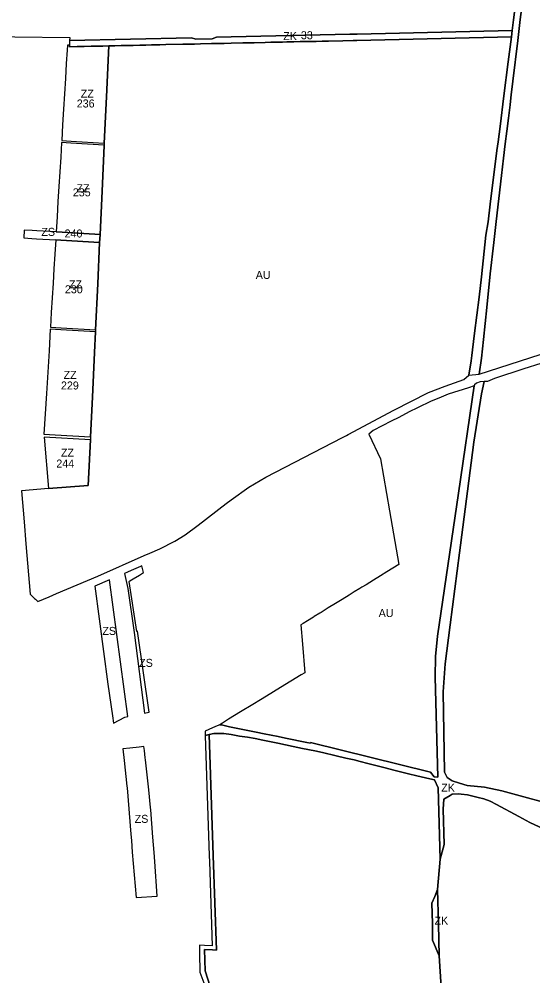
# Model space of a CAD drawing. Extents: x -521939 to -516426, y -1197857 to -1189551.
# Drawn here: x -519323 to -518681, y -1192149 to -1190954 of the extents above; entities that cross this region are included whole.
import ezdxf

# ---------------------------------------------------------------- set-up
doc = ezdxf.new("R2010")
doc.units = 0
for name, color, linetype in [('90660013', 7, 'Continuous'), ('90660023', 7, 'Continuous'), ('90670023', 7, 'Continuous'), ('90710013', 7, 'Continuous'), ('90710023', 7, 'Continuous'), ('90750013', 7, 'Continuous'), ('90760013', 7, 'Continuous'), ('ID_navrh', 7, 'Continuous')]:
    doc.layers.add(name, color=color, linetype=linetype)

msp = doc.modelspace()

# ---------------------------------------------------------------- linework, layer by layer
at = {"layer": '90660013'}
for points in [[(-519166.23, -1191821.08), (-519162.27, -1191820.28), (-519160.39, -1191819.9), (-519174.95, -1191718.57), (-519175.69, -1191719.09), (-519185.37, -1191656.34), (-519184.37, -1191655.72), (-519180.36, -1191653.25), (-519172.53, -1191648.41), (-519167.31, -1191645.19), (-519169.3, -1191636.96), (-519171.02, -1191637.8), (-519174.11, -1191639.14), (-519182.56, -1191642.78), (-519187.15, -1191644.77), (-519190.89, -1191646.39), (-519187.07, -1191665.36), (-519179.1, -1191720.15), (-519166.23, -1191821.08)], [(-519186.83, -1191825.25), (-519209.86, -1191654.59), (-519228.08, -1191662.46), (-519211.74, -1191784.69), (-519206.08, -1191824.4), (-519204.81, -1191833.46), (-519190.77, -1191826.05), (-519186.83, -1191825.25)], [(-519158.47, -1191938.79), (-519160.59, -1191916.77), (-519161.31, -1191909.45), (-519164.9, -1191879.38), (-519165.19, -1191876.73), (-519166.19, -1191867.57), (-519166.74, -1191862.69), (-519169.73, -1191863.03), (-519172.72, -1191863.37), (-519184.32, -1191864.69), (-519193.05, -1191865.68), (-519191.35, -1191880.2), (-519188.13, -1191912.11), (-519187.89, -1191914.5), (-519183.11, -1191972.15), (-519182.47, -1191980.22), (-519181.33, -1191994.8), (-519176.56, -1192051.51), (-519150.36, -1192049.88), (-519153.05, -1192006.54), (-519153.99, -1191995.08), (-519155.53, -1191975.95), (-519158.18, -1191941.83), (-519158.47, -1191938.79)]]:
    msp.add_lwpolyline(points, dxfattribs=at)
at = {"layer": '90660023'}
msp.add_lwpolyline([(-519277.03, -1191229.63), (-519270.66, -1191230.01), (-519222.12, -1191232.93), (-519221.9, -1191228.24), (-519221.65, -1191222.94), (-519269, -1191220.09), (-519276.43, -1191219.64), (-519300.38, -1191218.2), (-519306.37, -1191217.84), (-519316.35, -1191217.24), (-519316.95, -1191227.22), (-519306.97, -1191227.82), (-519300.98, -1191228.18), (-519277.03, -1191229.63)], dxfattribs=at)
at = {"layer": '90670023'}
for points in [[(-519269.55, -1191105.4), (-519257.89, -1191106.1), (-519216.29, -1191108.61), (-519213.59, -1191050.84), (-519210.6, -1190987.17), (-519218.24, -1190987.34), (-519232.69, -1190987.61), (-519241.28, -1190987.85), (-519250.24, -1190988.04), (-519259.96, -1190988.33), (-519259.89, -1190986.43), (-519262.38, -1190986.4), (-519262.74, -1190992.4), (-519263.74, -1191008.98), (-519264.88, -1191027.94), (-519266.03, -1191046.91), (-519267.2, -1191066.37), (-519268.37, -1191085.84), (-519269.55, -1191105.4)], [(-519269.7, -1191107.9), (-519270.8, -1191126.16), (-519271.9, -1191144.43), (-519273, -1191162.7), (-519274.14, -1191181.66), (-519275.28, -1191200.63), (-519276.43, -1191219.64), (-519269, -1191220.09), (-519221.65, -1191222.94), (-519219.11, -1191168.85), (-519216.44, -1191111.73), (-519216.41, -1191111.11), (-519258.03, -1191108.6), (-519269.7, -1191107.9)], [(-519277.03, -1191229.63), (-519278.11, -1191247.59), (-519279.19, -1191265.56), (-519280.27, -1191283.53), (-519281.38, -1191301.9), (-519282.48, -1191320.26), (-519283.59, -1191338.68), (-519270.38, -1191339.47), (-519227.23, -1191342.07), (-519227.23, -1191342.05), (-519224.53, -1191284.5), (-519222.12, -1191232.93), (-519270.66, -1191230.01), (-519277.03, -1191229.63)], [(-519233.5, -1191475.79), (-519231.17, -1191426.05), (-519228.55, -1191370.34), (-519227.35, -1191344.57), (-519270.52, -1191341.97), (-519283.74, -1191341.17), (-519285.37, -1191368.28), (-519286.98, -1191394.95), (-519288.59, -1191421.63), (-519290.11, -1191446.93), (-519291.64, -1191472.29), (-519277.54, -1191473.14), (-519233.5, -1191475.79)], [(-519285.93, -1191540.47), (-519236.33, -1191536.36), (-519233.67, -1191479.5), (-519291.33, -1191476), (-519285.93, -1191540.47)]]:
    msp.add_lwpolyline(points, dxfattribs=at)
at = {"layer": '90710013'}
for points in [[(-518701.87, -1190928.62), (-518705, -1190954.5), (-518706.73, -1190968.01), (-518707.73, -1190975.95), (-518711.69, -1191007.15), (-518717.06, -1191049.38), (-518721.96, -1191087.75), (-518724.35, -1191106.87), (-518725.79, -1191117.86), (-518734.23, -1191185.05), (-518736.94, -1191206.83), (-518739.49, -1191223.8), (-518745.15, -1191275.82), (-518748.04, -1191301.16), (-518750.85, -1191323.52), (-518753.72, -1191346.05), (-518756.3, -1191366.88), (-518757.28, -1191373.96), (-518758.12, -1191380.68), (-518760.85, -1191398.59), (-518747.87, -1191397.44), (-518744.99, -1191377.23), (-518742.65, -1191354.12), (-518738.65, -1191314.03), (-518734.1, -1191271.87), (-518729.7, -1191232.73), (-518726.85, -1191206.62), (-518720.19, -1191149.32), (-518717.56, -1191127.4), (-518715.46, -1191109.65), (-518713.5, -1191093.65), (-518711.56, -1191077.4), (-518709.5, -1191060.59), (-518707.98, -1191047.98), (-518706.78, -1191038.15), (-518705.95, -1191031.23), (-518699.77, -1190980.19), (-518696.61, -1190954.07), (-518693.43, -1190928.61)], [(-518754.2, -1191411.84), (-518773.85, -1191545.97), (-518800.05, -1191724.81), (-518802.68, -1191750.42), (-518803.08, -1191776.16), (-518799.63, -1191901.15), (-518804.16, -1191900.55), (-518808.94, -1191894.62), (-518958.64, -1191857.72), (-518958.57, -1191858.54), (-518963.29, -1191857.58), (-518989.74, -1191852.2), (-518999.26, -1191850.26), (-519016.52, -1191846.75), (-519026.54, -1191844.72), (-519043.1, -1191841.35), (-519059.82, -1191837.95), (-519068.41, -1191836.2), (-519072.06, -1191835.46), (-519077.48, -1191837.92), (-519085.67, -1191841.64), (-519090.29, -1191843.73), (-519090.29, -1191843.74), (-519090.12, -1191848.97), (-519085.16, -1191847.79), (-519079.37, -1191846.41), (-519066.92, -1191846.35), (-519057.75, -1191847.88), (-519047.43, -1191849.61), (-519037.5, -1191851.27), (-519028.03, -1191852.85), (-519018.37, -1191854.65), (-518999.64, -1191858.56), (-518989.78, -1191860.65), (-518980.39, -1191862.6), (-518968.88, -1191865.04), (-518953.17, -1191868.33), (-518943.85, -1191870.37), (-518926.69, -1191874.22), (-518914.51, -1191877.14), (-518904.31, -1191879.59), (-518896.54, -1191881.55), (-518887.24, -1191883.93), (-518865.4, -1191889.53), (-518854.47, -1191892.36), (-518836.4, -1191897), (-518825.73, -1191899.39), (-518809.6, -1191903.15), (-518803.99, -1191904.45), (-518799.28, -1191914.55), (-518796.83, -1192003.5), (-518791.91, -1191985.07), (-518793.12, -1191940.86), (-518792.23, -1191928.59), (-518784.35, -1191923.87), (-518781.86, -1191922.38), (-518774.41, -1191922.02), (-518770.47, -1191922.34), (-518762.46, -1191923.02), (-518749.45, -1191926.36), (-518742.23, -1191928.21), (-518734.3, -1191931.03), (-518726.43, -1191935.4), (-518698.42, -1191950.28), (-518684.53, -1191957.75), (-518662.07, -1191967.96)], [(-518640.22, -1191939.66), (-518719.73, -1191918.12), (-518741.25, -1191913.55), (-518763.14, -1191911.41), (-518772.54, -1191908.42), (-518781.94, -1191905.44), (-518787.95, -1191901.51), (-518791.36, -1191894.96), (-518792.8, -1191794.51), (-518790.3, -1191759.62), (-518784.24, -1191710.51), (-518772.41, -1191620.67), (-518762.61, -1191543.53), (-518754.85, -1191482.52), (-518745.17, -1191421.89), (-518741.69, -1191406.71), (-518746.71, -1191406.97), (-518751.45, -1191408.55), (-518753.93, -1191410.91), (-518754.2, -1191411.84)], [(-518797.81, -1192124.2), (-518798.92, -1192084.73), (-518800.13, -1192041.55), (-518800.16, -1192041.61), (-518803.56, -1192050.14), (-518806.95, -1192058.66), (-518806.95, -1192058.67), (-518806.52, -1192084.13), (-518806.17, -1192104.86), (-518797.81, -1192124.2)]]:
    msp.add_lwpolyline(points, dxfattribs=at)
at = {"layer": '90710023'}
for points in [[(-519259.89, -1190986.43), (-519259.96, -1190988.33), (-519250.24, -1190988.04), (-519241.28, -1190987.85), (-519232.69, -1190987.61), (-519218.24, -1190987.34), (-519210.6, -1190987.17), (-519202.99, -1190986.99), (-519195.39, -1190986.84), (-519180.12, -1190986.51), (-519171.98, -1190986.32), (-519164.58, -1190986.14), (-519157.3, -1190985.98), (-519146.73, -1190985.75), (-519139.45, -1190985.59), (-519118.38, -1190985.11), (-519103.75, -1190984.78), (-519096.18, -1190984.64), (-519082.46, -1190984.32), (-519074.13, -1190984.14), (-519066.62, -1190983.97), (-519057.96, -1190983.78), (-519043.29, -1190983.45), (-519036.25, -1190983.29), (-519029.04, -1190983.14), (-519015.53, -1190982.84), (-519008.2, -1190982.68), (-519001.41, -1190982.5), (-518993.81, -1190982.32), (-518988.21, -1190982.23), (-518979.42, -1190982.05), (-518971.69, -1190981.85), (-518960, -1190981.61), (-518951.6, -1190981.45), (-518943.98, -1190981.24), (-518936.34, -1190981.09), (-518918.12, -1190980.66), (-518905.51, -1190980.41), (-518900.98, -1190980.31), (-518707.73, -1190975.95), (-518706.73, -1190968.01), (-518900.54, -1190972.29), (-518905.06, -1190972.39), (-518909.73, -1190972.5), (-519076.07, -1190976.18), (-519081.68, -1190978.3), (-519101.85, -1190978.75), (-519107.55, -1190976.87), (-519259.67, -1190980.24), (-519259.89, -1190986.43)], [(-519083.86, -1192162.62), (-519090.14, -1192143.06), (-519091, -1192116.25), (-519081.24, -1192116.84), (-519076.23, -1192117.14), (-519080.14, -1191999.07), (-519085.16, -1191847.79), (-519090.12, -1191848.97), (-519085.14, -1191999.24), (-519084.89, -1192006.65), (-519081.41, -1192111.82), (-519091.16, -1192111.23), (-519097.51, -1192110.84), (-519097.34, -1192121.07), (-519096.85, -1192144.75), (-519088.41, -1192167.96)]]:
    msp.add_lwpolyline(points, dxfattribs=at)
at = {"layer": '90750013'}
for points in [[(-519397.29, -1190974.84), (-519259.53, -1190976.44), (-519259.67, -1190980.24), (-519107.55, -1190976.87), (-519101.85, -1190978.75), (-519081.68, -1190978.3), (-519076.07, -1190976.18), (-518909.73, -1190972.5), (-518905.06, -1190972.39), (-518900.54, -1190972.29), (-518706.73, -1190968.01), (-518705, -1190954.5), (-518701.87, -1190928.62)], [(-518693.43, -1190928.61), (-518696.61, -1190954.07), (-518699.77, -1190980.19), (-518705.95, -1191031.23), (-518706.78, -1191038.15), (-518707.98, -1191047.98), (-518709.5, -1191060.59), (-518711.56, -1191077.4), (-518713.5, -1191093.65), (-518715.46, -1191109.65), (-518717.56, -1191127.4), (-518720.19, -1191149.32), (-518726.85, -1191206.62), (-518729.7, -1191232.73), (-518734.1, -1191271.87), (-518738.65, -1191314.03), (-518742.65, -1191354.12), (-518744.99, -1191377.23), (-518747.87, -1191397.44), (-518607.36, -1191351.98)], [(-519233.5, -1191475.79), (-519233.67, -1191479.5), (-519236.33, -1191536.36), (-519285.93, -1191540.47), (-519319.78, -1191543.27), (-519316.54, -1191582.06), (-519314.27, -1191609.51), (-519309.03, -1191672.4), (-519303.32, -1191677.79), (-519302.34, -1191678.73), (-519299.42, -1191681.52), (-519285.21, -1191675.48), (-519275.99, -1191671.57), (-519224.33, -1191649.88), (-519166.49, -1191624.15), (-519159.42, -1191620.98), (-519146.78, -1191615.88), (-519128.1, -1191606.31), (-519115.32, -1191598.2), (-519099.08, -1191586.11), (-519064.09, -1191558.9), (-519057.88, -1191554.46), (-519035.9, -1191538.66), (-519014.69, -1191526.04), (-518918.69, -1191476.44), (-518913.57, -1191473.95), (-518911.56, -1191472.69), (-518854.76, -1191442.26), (-518811.46, -1191420.48), (-518790.63, -1191412.2), (-518767.05, -1191404.02), (-518760.85, -1191398.59), (-518758.12, -1191380.68), (-518757.28, -1191373.96), (-518756.3, -1191366.88), (-518753.72, -1191346.05), (-518750.85, -1191323.52), (-518748.04, -1191301.16), (-518745.15, -1191275.82), (-518739.49, -1191223.8), (-518736.94, -1191206.83), (-518734.23, -1191185.05), (-518725.79, -1191117.86), (-518724.35, -1191106.87), (-518721.96, -1191087.75), (-518717.06, -1191049.38), (-518711.69, -1191007.15), (-518707.73, -1190975.95), (-518900.98, -1190980.31), (-518905.51, -1190980.41), (-518918.12, -1190980.66), (-518936.34, -1190981.09), (-518943.98, -1190981.24), (-518951.6, -1190981.45), (-518960, -1190981.61), (-518971.69, -1190981.85), (-518979.42, -1190982.05), (-518988.21, -1190982.23), (-518993.81, -1190982.32), (-519001.41, -1190982.5), (-519008.2, -1190982.68), (-519015.53, -1190982.84), (-519029.04, -1190983.14), (-519036.25, -1190983.29), (-519043.29, -1190983.45), (-519057.96, -1190983.78), (-519066.62, -1190983.97), (-519074.13, -1190984.14), (-519082.46, -1190984.32), (-519096.18, -1190984.64), (-519103.75, -1190984.78), (-519118.38, -1190985.11), (-519139.45, -1190985.59), (-519146.73, -1190985.75), (-519157.3, -1190985.98), (-519164.58, -1190986.14), (-519171.98, -1190986.32), (-519180.12, -1190986.51), (-519195.39, -1190986.84), (-519202.99, -1190986.99), (-519210.6, -1190987.17), (-519213.59, -1191050.84), (-519216.29, -1191108.61), (-519216.41, -1191111.11), (-519216.44, -1191111.73), (-519219.11, -1191168.85), (-519221.65, -1191222.94), (-519221.9, -1191228.24), (-519222.12, -1191232.93), (-519224.53, -1191284.5), (-519227.23, -1191342.05), (-519227.23, -1191342.07), (-519227.35, -1191344.57), (-519228.55, -1191370.34), (-519231.17, -1191426.05), (-519233.5, -1191475.79)], [(-518754.2, -1191411.84), (-518761.48, -1191414.29), (-518786.77, -1191422.24), (-518798.48, -1191427.3), (-518808.08, -1191431.2), (-518824.92, -1191439.39), (-518835.63, -1191444.66), (-518848.51, -1191451.57), (-518857.88, -1191456.33), (-518880.29, -1191467.99), (-518885.93, -1191472.19), (-518871.38, -1191503.14), (-518860.03, -1191568.23), (-518848.35, -1191635.22), (-518855.68, -1191639.74), (-518863.57, -1191644.61), (-518871.47, -1191649.48), (-518880.15, -1191654.83), (-518889.34, -1191660.5), (-518894.63, -1191663.76), (-518897.28, -1191665.4), (-518904.04, -1191669.57), (-518909.18, -1191672.74), (-518910.35, -1191673.46), (-518919.14, -1191678.88), (-518927.34, -1191683.94), (-518936.55, -1191689.62), (-518945.5, -1191695.14), (-518947.13, -1191696.15), (-518954.06, -1191700.42), (-518955.12, -1191701.08), (-518962.41, -1191705.57), (-518968.04, -1191709.04), (-518970.94, -1191710.83), (-518968.91, -1191735.03), (-518965.94, -1191770.51), (-518970.55, -1191773.33), (-518996.05, -1191788.94), (-519004.95, -1191794.39), (-519019, -1191802.99), (-519021.11, -1191804.28), (-519030.85, -1191810.24), (-519046.06, -1191819.55), (-519061.07, -1191828.73), (-519068.8, -1191833.47), (-519072.06, -1191835.46), (-519068.41, -1191836.2), (-519059.82, -1191837.95), (-519043.1, -1191841.35), (-519026.54, -1191844.72), (-519016.52, -1191846.75), (-518999.26, -1191850.26), (-518989.74, -1191852.2), (-518963.29, -1191857.58), (-518958.57, -1191858.54), (-518958.64, -1191857.72), (-518808.94, -1191894.62), (-518804.16, -1191900.55), (-518799.63, -1191901.15), (-518803.08, -1191776.16), (-518802.68, -1191750.42), (-518800.05, -1191724.81), (-518773.85, -1191545.97), (-518754.2, -1191411.84)]]:
    msp.add_lwpolyline(points, dxfattribs=at)
at = {"layer": '90760013'}
for points in [[(-518671.16, -1191383.98), (-518692.08, -1191390.79), (-518728.9, -1191402.78), (-518737.43, -1191406.49), (-518741.69, -1191406.71), (-518745.17, -1191421.89), (-518754.85, -1191482.52), (-518762.61, -1191543.53), (-518772.41, -1191620.67), (-518784.24, -1191710.51), (-518790.3, -1191759.62), (-518792.8, -1191794.51), (-518791.36, -1191894.96), (-518787.95, -1191901.51), (-518781.94, -1191905.44), (-518772.54, -1191908.42), (-518763.14, -1191911.41), (-518741.25, -1191913.55), (-518719.73, -1191918.12), (-518640.22, -1191939.66)], [(-518797.81, -1192124.2), (-518806.17, -1192104.86), (-518806.52, -1192084.13), (-518806.95, -1192058.67), (-518806.95, -1192058.66), (-518803.56, -1192050.14), (-518800.16, -1192041.61), (-518796.83, -1192003.5), (-518799.28, -1191914.55), (-518803.99, -1191904.45), (-518809.6, -1191903.15), (-518825.73, -1191899.39), (-518836.4, -1191897), (-518854.47, -1191892.36), (-518865.4, -1191889.53), (-518887.24, -1191883.93), (-518896.54, -1191881.55), (-518904.31, -1191879.59), (-518914.51, -1191877.14), (-518926.69, -1191874.22), (-518943.85, -1191870.37), (-518953.17, -1191868.33), (-518968.88, -1191865.04), (-518980.39, -1191862.6), (-518989.78, -1191860.65), (-518999.64, -1191858.56), (-519018.37, -1191854.65), (-519028.03, -1191852.85), (-519037.5, -1191851.27), (-519047.43, -1191849.61), (-519057.75, -1191847.88), (-519066.92, -1191846.35), (-519079.37, -1191846.41), (-519085.16, -1191847.79), (-519080.14, -1191999.07), (-519076.23, -1192117.14), (-519081.24, -1192116.84), (-519091, -1192116.25), (-519090.14, -1192143.06), (-519083.86, -1192162.62)], [(-518662.07, -1191967.96), (-518684.53, -1191957.75), (-518698.42, -1191950.28), (-518726.43, -1191935.4), (-518734.3, -1191931.03), (-518742.23, -1191928.21), (-518749.45, -1191926.36), (-518762.46, -1191923.02), (-518770.47, -1191922.34), (-518774.41, -1191922.02), (-518781.86, -1191922.38), (-518784.35, -1191923.87), (-518792.23, -1191928.59), (-518793.12, -1191940.86), (-518791.91, -1191985.07), (-518796.83, -1192003.5), (-518800.16, -1192041.61), (-518800.13, -1192041.55), (-518798.92, -1192084.73), (-518797.81, -1192124.2), (-518777.54, -1192443.31)], [(-518777.54, -1192443.31), (-518797.81, -1192124.2)]]:
    msp.add_lwpolyline(points, dxfattribs=at)

# ---------------------------------------------------------------- texts
at = {"layer": '90660013'}
for rotation, p in [(0, (-519218.77, -1191723.28)), (360, (-519172.78, -1191763.21)), (0, (-519178.36, -1191958.14))]:
    msp.add_text('ZS', height=10, rotation=rotation, dxfattribs=at).set_placement(p)
at = {"layer": '90660023'}
msp.add_text('ZS', height=10, rotation=360, dxfattribs=at).set_placement((-519294.93, -1191224.55))
at = {"layer": '90670023'}
for rotation, p in [(0, (-519245.74, -1191051.83)), (0, (-519251.05, -1191169.97)), (360, (-519260.48, -1191290.14)), (0, (-519267.19, -1191403.35)), (360, (-519270.52, -1191500.56))]:
    msp.add_text('ZZ', height=10, rotation=rotation, dxfattribs=at).set_placement(p)
at = {"layer": '90710013'}
for p in [(-518795.45, -1191919.21), (-518803.82, -1192085.34)]:
    msp.add_text('ZK', height=10, rotation=360, dxfattribs=at).set_placement(p)
at = {"layer": '90710023'}
msp.add_text('ZK', height=10, rotation=360, dxfattribs=at).set_placement((-518992.84, -1190979.9))
at = {"layer": '90750013'}
for p in [(-519027.11, -1191278.38), (-518873.58, -1191700.93)]:
    msp.add_text('AU', height=10, rotation=0, dxfattribs=at).set_placement(p)
at = {"layer": 'ID_navrh'}
for s, rotation, p in [('33', 360, (-518970.73, -1190978.82)), ('236', 0, (-519250.73, -1191064.12)), ('235', 0, (-519255.64, -1191175.14)), ('240', 0, (-519265.89, -1191226.57)), ('230', 360, (-519265.54, -1191296.31)), ('229', 0, (-519270.45, -1191416.53)), ('244', 360, (-519276.25, -1191514.1))]:
    msp.add_text(s, height=10, rotation=rotation, dxfattribs=at).set_placement(p)

doc.saveas('drawing.dxf')
